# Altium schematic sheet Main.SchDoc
size 152 x 127 mm
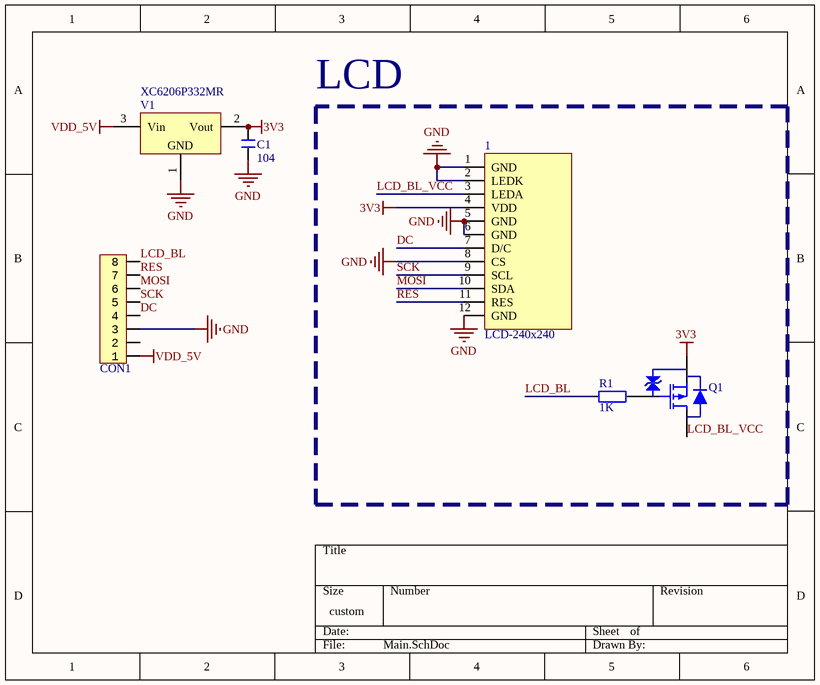
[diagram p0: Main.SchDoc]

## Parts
1  LCD-240x240  [LCD-240x240-NoHole]
C1  104  [C 0402_M]
CON1  FFC_0.5_8  [FFC_0.5_8]  (value not drawn)
Q1  AO3415A  [SOT23-3]  (value not drawn)
R1  1K  [RES_0402]
V1  XC6206P332MR  [SOT23-3L]

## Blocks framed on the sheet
LCD: 1 Q1 R1

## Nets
3V3: 1.4(VDD) C1.2 Q1.2(S) V1.2(Vout)
GND: 1.1(GND) 1.2(LEDK) 1.5(GND) 1.6(GND) 1.8(CS) 1.12(GND) C1.1 CON1.3 V1.1(GND)
VDD_5V: CON1.1 V1.3(Vin)
DC: 1.7(D/C) CON1.4
LCD_BL: CON1.8 R1.1
LCD_BL_VCC: 1.3(LEDA) Q1.3(D)
MOSI: 1.10(SDA) CON1.6
RES: 1.11(RES) CON1.7
SCK: 1.9(SCL) CON1.5
NetQ1_1: Q1.1(G) R1.2

Not connected (* = marked no-connect by the designer): CON1 2

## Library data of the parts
1 = LCD-240x240: 显示屏
C1 = C: 无极性贴片电容; 材质: X7R
CON1 = FFC_0.5_8: FFC; System: Connector
Q1 = AO3415A: MOSFET
R1 = 电阻-0402: Resistor; Value: 22R
V1 = XC6206P332MR: 低压差线性稳压芯片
